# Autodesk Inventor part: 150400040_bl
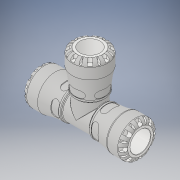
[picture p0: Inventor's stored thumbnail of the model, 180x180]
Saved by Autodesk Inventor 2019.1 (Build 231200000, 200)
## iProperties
Created: 2016-12
Part Number: 150400040_bl
Material: Generic
Description: PLASSON G-PLASS TEE 40X40X40
Document SubType Name: Modeling
Designer: KIM
Mass: 664.223 g
Surface Area: 733.008 cm^2
Volume: 474.445 cm^3
Density: 1 g/cm^3
Appearance: Default
Author: KIM
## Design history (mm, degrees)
derived "150400.ipt"
feature "Solid1::150400.ipt" dims "ScaleForDerivedMember" = 10
tag "TaggingFeature1"
body "Solid1"
other parameters: "l_" = 74 [user parameter], "A_" = 111 [user parameter], "H_" = 198 [user parameter], "d9" = 10 [user parameter], "d1" = 31.08 [user parameter], "d8" = 59.5 [user parameter], "d13" = 8 [user parameter], "d14" = 8 [user parameter], "d15" = 0 [user parameter], "d17" = 360 deg [user parameter], "d19" = 8 deg [user parameter], "d20" = 0.8 [user parameter], "d21" = 0.8 [user parameter], "d22" = 8 deg [user parameter], "d24" = 0 [user parameter], "d26" = 360 deg [user parameter], "d33" = 7 [user parameter], "d43" = 54.6 [user parameter], "d51" = 0.7 [user parameter], "d54" = 14 [user parameter], "d55" = 8.8 [user parameter], "d57" = 15.68 [user parameter], "d58" = 0 [user parameter], "d74" = 0 [user parameter], "d77" = 3.33333 [user parameter], "d78" = 74 [user parameter], "d79" = 54.6 [user parameter], "d80" = 198 [user parameter], "d82" = 0.8 [user parameter], "d115" = 360 deg [user parameter], "d139" = 8 [user parameter], "d140" = 0 [user parameter], "d142" = 360 deg [user parameter], "d207" = 90 deg [user parameter], "d209" = 31.08 [user parameter], "d213" = 59.5 [user parameter], "d215" = 54.6 [user parameter], "d216" = 3.33333 [user parameter], "d217" = 74 [user parameter], "d225" = 111 [user parameter], "d226" = 74 [user parameter], "d228" = 11.9 [user parameter], "d229" = 8 [user parameter], "d233" = 8 [user parameter], "d234" = 0 [user parameter], "d236" = 360 deg [user parameter], "d238" = 8 deg [user parameter], "d239" = 8 deg [user parameter], "d240" = 0.8 [user parameter], "d241" = 0.8 [user parameter], "d243" = 0 [user parameter], "d245" = 360 deg [user parameter], "d247" = 1.4 [user parameter], "d248" = 4.44 [user parameter], "d249" = 4.44 [user parameter], "d250" = 11.9 [user parameter], "d252" = 14 [user parameter], "d253" = 9.2 [user parameter], "d254" = 15.68 [user parameter], "d255" = 0 [user parameter], "d257" = 360 deg [user parameter], "d259" = 0.8 [user parameter], "d261" = 0 [user parameter], "d262" = 1.4 [user parameter], "d264" = 0 [user parameter], "d266" = 0 [user parameter], "d267" = 0.7 [user parameter]
